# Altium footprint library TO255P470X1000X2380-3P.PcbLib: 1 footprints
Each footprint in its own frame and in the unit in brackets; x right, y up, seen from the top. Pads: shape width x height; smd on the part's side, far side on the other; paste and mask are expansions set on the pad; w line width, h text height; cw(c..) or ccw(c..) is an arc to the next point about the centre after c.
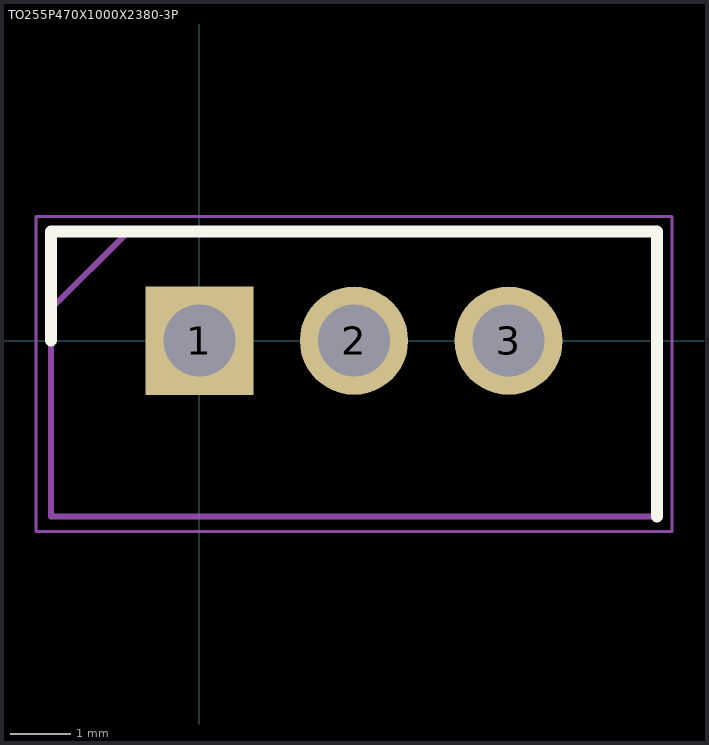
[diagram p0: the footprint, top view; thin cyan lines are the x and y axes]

## TO255P470X1000X2380-3P [mm]
pads (3):
  rect 1.785x1.785 / inner round 1.785 / far side rect 1.785x1.785 hole 1.19: 1(0,0)
  round 1.785 hole 1.19: 2(2.55,0) 3(5.1,0)
Top Overlay:
  lines w0.2: -2.45,0 -2.45,1.8 7.55,1.8 7.55,-2.9
Mechanical 15:
  lines w0.1: -2.45,0.525 -1.175,1.8 ; -2.45,-2.9 7.55,-2.9 7.55,1.8 -2.45,1.8 -2.45,-2.9
Mechanical 20:
  lines w0.05: -2.7,-3.15 7.8,-3.15 7.8,2.05 -2.7,2.05 -2.7,-3.15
